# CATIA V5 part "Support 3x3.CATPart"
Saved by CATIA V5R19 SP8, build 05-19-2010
Part number: Bracket 3x3
Definition: Bracket 3x3
Nomenclature: 61500
Material "Aluminium": density 2710 kg/m3, Young's modulus 7e+10 Pa, Poisson ratio 0.346, thermal expansion 2.36e-05 1/K
Bounding box of the stored display mesh (mm): x -12 to 12, y 0 to 26, z 0 to 26
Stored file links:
  D:\Documents\1_Travail\1 - ac-limoges.fr\ac-limoges.fr\Emmanuel Maynard - STI2D_Turgot\1 - IT-I2D\Activités_IT_Première\IT_3_Abris_bus\Maquettes numériques\Abribus_eleve\Support 3x3.CATPart
  C:\Program Files\Dassault Systemes\B19\win_b64\startup\materials\French\Catalog.CATMaterial
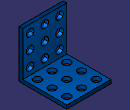
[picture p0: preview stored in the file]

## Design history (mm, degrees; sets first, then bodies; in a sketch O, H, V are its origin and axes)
AxisSystem1: origin (0, 0, 0), X (1, 0, 0), Y (0, 1, 0), Z (0, 0, 1)
Body1 (main body), material "Aluminium"
  Sketch1 on YZ plane of AxisSystem1, origin (0, 0, 0), H (0, 1, 0), V (0, 0, 1)
    point P1 (0, 26)
    line L1 (0, 26) -> (0, 0)
    line L2 (0, 0) -> (26, 0)
    length L2 = 26
    length L1 = 26
    coincidence: P1 V
    vertical: L1 V
    horizontal: L2 H
  Pad1: profile Sketch1, direction (1, 0, 0), length 4, mirrored extent, thin wall 2
  Sketch2 on face of Pad1, origin (0.0588, 2, 22.8746), H (1, 0, 0), V (0, 0, -1)
    point P1 (-0.0588, 0.8746)
    reference intersected line E1 (3.9412, -3.1254) -> (-4.0588, -3.1254) from face of Pad1
    reference projected line E2 (-4.0588, -3.1254) -> (-4.0588, 20.8746) from edge [face of Pad1 | start face of Pad1]
    distance P1 E1 = 4
    distance P1 E2 = 4
  Hole1: placed by Sketch2, at (0, 2, 22) direction (0, -1, 0), diameter 4.1, depth 10
  RectPattern1: of Hole1, direction 1 instances 3, spacing 8, along edge [end face of Pad1 | face of Pad1]
  Sketch3 on face of Pad1, origin (-0.3777, 22.8432, 2), H (1, 0, 0), V (0, 1, 0)
    point P1 (0.3777, -0.8432)
    reference intersected line E1 (-3.6223, 3.1568) -> (4.3777, 3.1568) from face of Pad1
    reference projected line E2 (-3.6223, -20.8432) -> (-3.6223, 3.1568) from edge [face of Pad1 | start face of Pad1]
    distance P1 E1 = 4
    distance P1 E2 = 4
  Hole2: placed by Sketch3, at (0, 22, 2) direction (0, 0, -1), diameter 4.1, depth 10
  RectPattern2: of Hole2, direction 1 instances 3, spacing 8, along edge [end face of Pad1 | face of Pad1] reversed
  RectPattern3: of the body so far, direction 1 instances 3, spacing 8, along edge [XY plane of AxisSystem1 | ZX plane of AxisSystem1], Nu 2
